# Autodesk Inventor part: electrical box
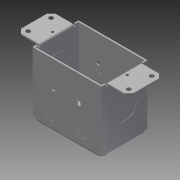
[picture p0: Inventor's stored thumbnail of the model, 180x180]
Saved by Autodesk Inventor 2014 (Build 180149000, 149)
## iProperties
Created: 2008-02
Material: Steel, Mild
Document SubType Name: Sheet Metal
Designer: MSD
Density: 7.86 g/cm^3
Flat Pattern Width: 18.5216 cm
Flat Pattern Length: 25.7113 cm
Flat Pattern Area: 476.213 cm^2
Sheet Metal Rule: Steel 16 Ga
Appearance: Steel
Length: =<FLAT PATTERN LENGTH> cm
Width: =<FLAT PATTERN WIDTH> cm
Author: Autodesk, Inc.
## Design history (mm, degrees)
node "Face1"
  sketch "Sketch1"
    geometry: L1 (-38.1, 25.4)-(-38.1, -25.4); L2 (-38.1, -25.4)-(38.1, -25.4); L3 (38.1, -25.4)-(38.1, 25.4); L4 (38.1, 25.4)-(-38.1, 25.4); L5 (38.1, -25.4)-(-38.1, 25.4); 2 further points
    constraints: 10 end point, 2 parallel, 1 coincident, 1 midpoint, 1 perpendicular, 1 vertical
    dimensions: "d0" = 76.2 distance of L1.end L2.end; "d1" = 50.8 distance of L2.end L3.end
node "Flange1"
node "Flange2"
node "Flange3"
feature "Corner Chamfer1" dims "d51" = 4.7752, "d52" = 6.35, angle "d53" = 45 deg
sketch "Sketch5"
  geometry: L1 (74.808, 44.45)-(2.154, 44.45) reference; L2 (0.381, -6.35)-(76.581, -6.35) reference; L3 (0.381, 44.45)-(0.381, -6.35) reference; L4 (76.581, 44.45)-(0.381, 44.45) reference; L5 (0.381, 44.45)-(76.581, -6.35); L6 (76.581, -6.35)-(76.581, 44.45) reference; L7 (-2.794, 19.05)-(79.756, 19.05); 3 further points
  constraints: 4 end point, 2 coincident, 2 midpoint, 1 perpendicular
  dimensions: "d54" = 82.55 distance of L7.start L7.end
hole "Hole1" sketch "Sketch5" at (-2.794, 19.05), (79.756, 19.05) diameter "d55" = 2.6416; stored, may be unused: countersink angle "d59" = 82 deg, drill point angle "d61" = 118 deg; dims "d56" = 12.7, "d57" = 9.525, "d58" = 6.35, "d60" = 1.51892 (= Thickness)
sketch "Sketch6" dims "d64" = 4.7752
  geometry: L1 (-103.408, 19.05)-(-103.408, -19.05) reference; L2 (-105.056, 19.05)-(-105.056, -19.05) reference; L3 (-104.232, -19.05)-(-104.232, 19.05) reference; L4 (-38.501, -21.778)-(-38.501, 21.778) reference; L5 (-35.057, 22.001)-(-35.057, -22.001) reference; L6 (34.678, 22.357)-(-34.678, 22.357) reference; L7 (-103.408, -20.569)-(-105.308, -20.569) reference; L8 (-105.308, -25.4)-(-105.308, -20.569) reference; L9 (-39.803, -25.4)-(-105.308, -25.4) reference; L10 (-105.308, 25.4)-(-39.803, 25.4) reference; L11 (-123.781, -19.05)-(-105.056, -19.05) reference; L12 (-105.056, 19.05)-(-123.781, 19.05) reference; L13 (-123.781, -19.05)-(-128.556, -14.275) reference; L14 (-105.308, 20.569)-(-105.308, 25.4) reference; L15 (-105.308, 20.569)-(-103.408, 20.569) reference; L16 (-103.408, -19.05)-(-105.056, -19.05) reference; L17 (-34.678, -22.357)-(34.678, -22.357) reference; L18 (-103.408, 19.05)-(-105.056, 19.05) reference; L19 (35.057, -22.001)-(35.057, 22.001) reference; L20 (-128.556, 14.275)-(-123.781, 19.05) reference; L21 (-128.556, 14.275)-(-128.556, -14.275) reference; L22 (-36.779, 21.351)-(-36.779, -21.351) reference; L23 (103.408, -19.05)-(103.408, 19.05) reference; L24 (104.232, 19.05)-(104.232, -19.05) reference; L25 (38.501, 21.778)-(38.501, -21.778) reference; L26 (123.781, 19.05)-(128.556, 14.275) reference; L27 (123.781, 19.05)-(105.056, 19.05) reference; L28 (105.056, -19.05)-(123.781, -19.05) reference; L29 (128.556, -14.275)-(128.556, 14.275) reference; L30 (105.056, -19.05)-(105.056, 19.05) reference; L31 (103.408, 20.569)-(105.308, 20.569) reference; L32 (105.308, 25.4)-(105.308, 20.569) reference; L33 (39.803, 25.4)-(105.308, 25.4) reference; L34 (105.308, -25.4)-(39.803, -25.4) reference; L35 (105.308, -20.569)-(105.308, -25.4) reference; L36 (105.308, -20.569)-(103.408, -20.569) reference; L37 (103.408, 19.05)-(105.056, 19.05) reference; L38 (103.408, -19.05)-(105.056, -19.05) reference; L39 (128.556, -14.275)-(123.781, -19.05) reference; L40 (36.779, -21.351)-(36.779, 21.351) reference; L41 (-34.253, 25.801)-(34.253, 25.801) reference; L42 (-36.327, 92.608)-(36.327, 92.608) reference; L43 (33.918, 24.079)-(-33.918, 24.079) reference; L44 (36.327, 92.608)-(36.327, 27.36) reference; L45 (-36.327, 27.36)-(-36.327, 92.608) reference; L46 (34.253, -25.801)-(-34.253, -25.801) reference; L47 (36.327, -27.36)-(36.327, -92.608) reference; L48 (36.327, -92.608)-(-36.327, -92.608) reference; L49 (-36.327, -92.608)-(-36.327, -27.36) reference; L50 (-33.918, -24.079)-(33.918, -24.079) reference; L51 (12.7, 64.033)-(-12.7, 64.033); L52 (0, 92.608)-(0, 25.801); L53 (-122.206, 12.7)-(-122.206, -12.7); L54 (-128.556, 0)-(-38.501, 0); L55 (0, 21.713)-(0, -22.357); L56 (-35.057, 0)-(35.057, 0); L57 (-12.7, 0)-(12.7, 0); C1 r 2.388 at (-12.7, 64.033); C2 r 2.388 at (-122.206, 12.7); C3 r 2.388 at (-122.206, -12.7); C4 r 2.388 at (-12.7, -64.033); C5 r 2.388 at (15.088, -64.033); C6 r 2.388 at (122.206, 12.7); C7 r 2.388 at (122.206, -12.7); C8 r 2.388 at (-12.7, 0); C9 r 2.388 at (12.7, 0); A1 r 0.759 centre (-103.408, 19.809) between (-103.408, 19.05) and (-103.408, 20.569) reference; A2 r 0.759 centre (-103.408, -19.809) between (-103.408, -20.569) and (-103.408, -19.05) reference; A3 r 1.321 centre (-107.85, 0) between (-109.171, 0) and (-109.171, 0) reference; A4 r 0.759 centre (103.408, 19.809) between (103.408, 20.569) and (103.408, 19.05) reference; A5 r 0.759 centre (103.408, -19.809) between (103.408, -19.05) and (103.408, -20.569) reference; A6 r 1.321 centre (107.85, 0) between (106.529, 0) and (106.529, 0) reference; A7 r 3.038 centre (36.94, 24.385) between (36.327, 27.36) and (39.803, 25.4) reference; A8 r 3.038 centre (-36.94, 24.385) between (-39.803, 25.4) and (-36.327, 27.36) reference; A9 r 3.038 centre (-36.94, -24.385) between (-36.327, -27.36) and (-39.803, -25.4) reference; A10 r 3.038 centre (36.94, -24.385) between (39.803, -25.4) and (36.327, -27.36) reference; 3 further points
  constraints: 14 end point, 9 centre point, 9 midpoint, 4 point on line, 4 symmetric about line, 2 parallel, 1 coincident, 1 collinear, 1 horizontal alignment, 11 other
  dimensions: "d62" = 25.4 distance of L51.start L51.end; "d63" = 28.575 distance between parallel lines of L51 L42; "d65" = 6.35 distance between parallel lines of L21 L53; "d66" = 25.4 distance of L53.start L53.end; "d67" = 25.4 distance of L57.start L57.end (= d62)
cut "Cut1" sketch "Sketch6" dims "d68" = 1.51892 (= Thickness), "d69" = 0
sketch "Sketch7"
  geometry: L1 (0, 0)-(72.654, 0) reference; L2 (18.852, -47.752)-(53.802, -47.752); L3 (36.327, 0)-(36.327, -47.752); 1 further point
  constraints: 4 end point, 2 midpoint, 1 coincident, 1 horizontal, 1 perpendicular
  dimensions: "d70" = 47.752 distance from line of L2.start L1; "d71" = 17.4752 distance from line of L3 L2.start
feature "iFeature3:1" sketch "Sketch7" dims "d97" = 22.2504, "d98" = 6.35 (= 2 x d99), "d99" = 3.175, "d100" = 12.7
sketch "Sketch8"
  geometry: 2 further points
feature "iFeature3:2" sketch "Sketch8" dims "d102" = 22.2504, "d103" = 6.35 (= 2 x d104), "d104" = 3.175, "d105" = 12.7
sketch "Sketch10"
  geometry: L1 (-1.014, -3.824)-(-66.807, -3.824) reference; L2 (-66.807, -3.824)-(-66.807, 1.007) reference; 1 further point
  dimensions: "d87" = 25.4 distance from line of point (-35.057, 21.576) L1; "d88" = 31.75 distance from line of point (-35.057, 21.576) L2
feature "iFeature2:1" sketch "Sketch10" dims "d89" = 27.7876, "d90" = 3.175, "d91" = 15.4686
sketch "Sketch11"
  geometry: 1 further point
feature "iFeature2:2" sketch "Sketch11" dims "d93" = 27.7876, "d94" = 3.175, "d95" = 15.4686
body "Solid1"
face "Plate2" dims "Thickness" = 1.51892 (derived)
sketch "Sketch2"
  geometry: L1 through (-25.4, 0) direction (1, 0); L2 through (0, 34.925) direction (-5.56e-33, 1); L3 (0, 69.85)-(-50.8, 69.85); L4 (-50.8, 69.85)-(-50.8, 0)
  constraints: 6 end point, 1 horizontal, 1 perpendicular, 1 vertical
face "Plate3" dims "d13" = 1.51892 (= BendReliefWidth), "d14" = 0.75946 (= BendReliefDepth), "d15" = 3.03784 (= MinimumRemnant), "d16" = 1.524 (= BendRadius), "d17" = 69.85, "d18" = 90 deg, "d19" = 1.524 (= BendRadius), "d20" = 6.07568 (= CornerReliefSize), "d21" = 0.254, "d22" = 1.524 (= JacobiRadiusSize), "d23" = 10, "d24" = 10, "d25" = 10, "d26" = 10, "SeamGap" = 0.00508, "Thickness" = 1.51892 (derived)
bend "Bend2" dims "d13" = 1.51892 (= BendReliefWidth), "d14" = 0.75946 (= BendReliefDepth), "d15" = 3.03784 (= MinimumRemnant), "d16" = 1.524 (= BendRadius), "d17" = 69.85, "d18" = 90 deg, "d19" = 1.524 (= BendRadius), "SeamGap" = 0.00508, "Thickness" = 1.51892 (derived)
feature "Corner2" dims "d17" = 69.85, "d18" = 90 deg, "d20" = 6.07568 (= CornerReliefSize), "d21" = 0.254, "d22" = 1.524 (= JacobiRadiusSize)
sketch "Sketch3"
  geometry: L1 (0, 44.45)-(0, 6.35); L2 (0, 6.35)-(25.4, 6.35); L3 (25.4, 6.35)-(25.4, 44.45); L4 (25.4, 44.45)-(0, 44.45)
  constraints: 8 end point
face "Plate4" dims "d27" = 1.51892 (= BendReliefWidth), "d28" = 0.75946 (= BendReliefDepth), "d29" = 3.03784 (= MinimumRemnant), "d30" = 1.524 (= BendRadius), "d31" = 6.35, "d32" = 6.35, "d33" = 25.4, "d34" = 90 deg, "d35" = 0.381, "d36" = 6.07568 (= CornerReliefSize), "d37" = 1.51892 (= Thickness), "d38" = 1.524 (= JacobiRadiusSize), "SeamGap" = 0.00508, "Thickness" = 1.51892 (derived)
bend "Bend3" dims "d27" = 1.51892 (= BendReliefWidth), "d28" = 0.75946 (= BendReliefDepth), "d29" = 3.03784 (= MinimumRemnant), "d30" = 1.524 (= BendRadius), "d33" = 25.4, "d34" = 90 deg, "d35" = 0.381, "SeamGap" = 0.00508, "Thickness" = 1.51892 (derived)
feature "Corner3" dims "d33" = 25.4, "d34" = 90 deg, "d36" = 6.07568 (= CornerReliefSize), "d37" = 1.51892 (= Thickness), "d38" = 1.524 (= JacobiRadiusSize)
sketch "Sketch4"
  geometry: L1 (0, -44.45)-(0, -6.35); L2 (0, -6.35)-(-25.4, -6.35); L3 (-25.4, -6.35)-(-25.4, -44.45); L4 (-25.4, -44.45)-(0, -44.45)
  constraints: 8 end point
face "Plate5" dims "d39" = 1.51892 (= BendReliefWidth), "d40" = 0.75946 (= BendReliefDepth), "d41" = 3.03784 (= MinimumRemnant), "d42" = 1.524 (= BendRadius), "d43" = 6.35, "d44" = 6.35, "d45" = 25.4, "d46" = 90 deg, "d47" = 0.381, "d48" = 6.07568 (= CornerReliefSize), "d49" = 1.51892 (= Thickness), "d50" = 1.524 (= JacobiRadiusSize), "SeamGap" = 0.00508, "Thickness" = 1.51892 (derived)
bend "Bend4" dims "d39" = 1.51892 (= BendReliefWidth), "d40" = 0.75946 (= BendReliefDepth), "d41" = 3.03784 (= MinimumRemnant), "d42" = 1.524 (= BendRadius), "d45" = 25.4, "d46" = 90 deg, "d47" = 0.381, "SeamGap" = 0.00508, "Thickness" = 1.51892 (derived)
feature "Corner4" dims "d45" = 25.4, "d46" = 90 deg, "d48" = 6.07568 (= CornerReliefSize), "d49" = 1.51892 (= Thickness), "d50" = 1.524 (= JacobiRadiusSize)
feature "Definition1"
other parameters: "BendRadius" = 1.524 (derived), "BendReliefWidth" = 1.51892 (= Thickness), "BendReliefDepth" = 0.75946 (= 0.5 x Thickness), "CornerReliefSize" = 6.07568 (= 4 x Thickness), "MinimumRemnant" = 3.03784 (= 2 x Thickness), "TransitionRadius" = 1.524 (= BendRadius), "JacobiRadiusSize" = 1.524 (= BendRadius), "d12" = 1.524 (= BendRadius), "d92" = 180 deg, "d96" = 180 deg, "d101" = 0, "d106" = 0, "GapSize" = 1.51892 (= Thickness), "BendRadius" = 1.524, "BendReliefDepth" = 0.75946, "BendReliefWidth" = 1.51892, "CornerReliefSize" = 6.07568, "JacobiRadiusSize" = 1.524, "MinimumRemnant" = 3.03784, "Thickness" = 1.51892, "TransitionRadius" = 1.524, "GapSize" = 1.51892
